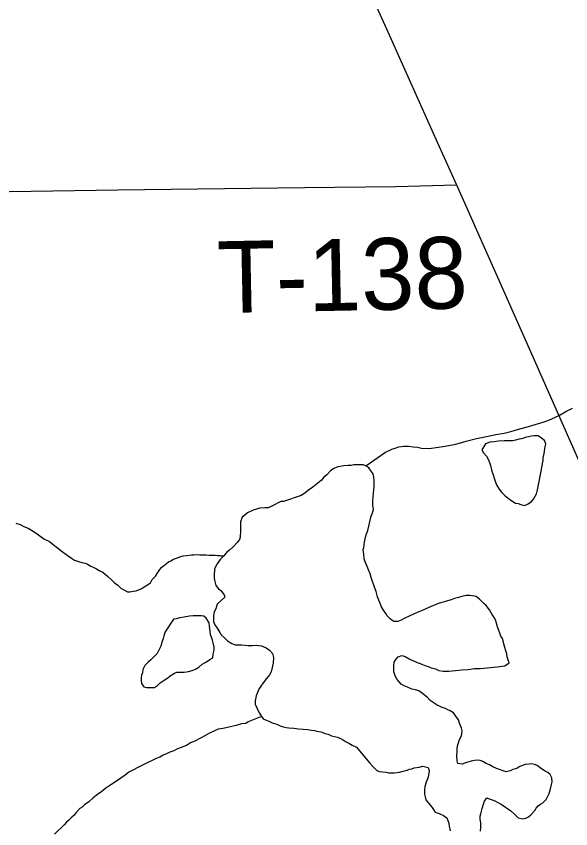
# Model space of a CAD drawing. Extents: x 10.6 to 44.6, y -2.6 to 23.4.
# Drawn here: x 19.078 to 19.517, y 20.958 to 21.601 of the extents above; entities that cross this region are included whole.
import ezdxf

# ---------------------------------------------------------------- set-up
doc = ezdxf.new("R2010")
doc.units = 0
for name, color, linetype in [('GM_X_Minor_Lake', 7, 'Continuous'), ('GM_X_Minor_River', 7, 'Continuous'), ('GM_X_State_Route', 7, 'Continuous'), ('GM_X_Township_Road', 7, 'Continuous'), ('GM_X_Township_Road_Text', 7, 'Continuous')]:
    doc.layers.add(name, color=color, linetype=linetype)

msp = doc.modelspace()

# ---------------------------------------------------------------- linework, layer by layer
at = {"layer": 'GM_X_Minor_Lake'}
for points in [[(19.49489, 21.24647), (19.49496, 21.24686), (19.49532, 21.24914), (19.49531, 21.25142), (19.49604, 21.25484), (19.4964, 21.25675), (19.49677, 21.25865), (19.4975, 21.26245), (19.49634, 21.2651), (19.49405, 21.26699), (19.49138, 21.26887), (19.48834, 21.26884), (19.48606, 21.26845), (19.48379, 21.26805), (19.4819, 21.26766), (19.48001, 21.26688), (19.47811, 21.26649), (19.47622, 21.26609), (19.47357, 21.26532), (19.47129, 21.26492), (19.46826, 21.2649), (19.46446, 21.26487), (19.45991, 21.26446), (19.4565, 21.26405), (19.45309, 21.26365), (19.44968, 21.26248), (19.44672, 21.25759)], [(19.44672, 21.25759), (19.44821, 21.25525), (19.45051, 21.25261), (19.45167, 21.25034), (19.45283, 21.24769), (19.4536, 21.24541), (19.45478, 21.24086), (19.45556, 21.23859), (19.45673, 21.23442), (19.4575, 21.23215), (19.45866, 21.22949), (19.46097, 21.22571), (19.4625, 21.22383), (19.46518, 21.22119), (19.46861, 21.21855), (19.47128, 21.21667), (19.47357, 21.21555), (19.47547, 21.21518), (19.47775, 21.21444), (19.4808, 21.2137), (19.48344, 21.21486), (19.48608, 21.21678), (19.48759, 21.21869), (19.48909, 21.22098), (19.49021, 21.22289), (19.49095, 21.22593), (19.49131, 21.22859), (19.49204, 21.23126), (19.49489, 21.24647)], [(19.45914, 21.11743), (19.45836, 21.12046), (19.45758, 21.12311), (19.45643, 21.125), (19.45489, 21.12727), (19.45297, 21.13106), (19.45028, 21.13446), (19.44838, 21.13596), (19.44493, 21.13936), (19.44226, 21.14162), (19.43922, 21.14198), (19.43732, 21.14234), (19.43428, 21.14232), (19.43087, 21.14153), (19.42822, 21.14075), (19.42519, 21.13997), (19.42255, 21.13881), (19.41952, 21.13803), (19.41724, 21.13725), (19.41497, 21.13686), (19.41232, 21.13608), (19.40967, 21.13492), (19.40665, 21.13376), (19.40249, 21.13183), (19.39908, 21.13028), (19.39605, 21.12912), (19.38584, 21.12449), (19.38282, 21.12295), (19.38017, 21.12179), (19.37713, 21.12176), (19.37446, 21.12364), (19.37179, 21.12628), (19.37063, 21.12817), (19.36871, 21.13082), (19.36718, 21.13347), (19.36563, 21.13726), (19.36408, 21.14142), (19.36291, 21.14559), (19.36174, 21.14901), (19.36097, 21.15128), (19.36019, 21.15355), (19.35903, 21.15658), (19.35824, 21.15962), (19.35708, 21.16265), (19.35592, 21.1653), (19.35515, 21.16719), (19.35438, 21.16909), (19.3536, 21.17136), (19.35319, 21.17516), (19.35279, 21.17857), (19.35315, 21.18048), (19.35352, 21.18238), (19.35388, 21.18466), (19.35461, 21.18846), (19.35535, 21.19113), (19.35646, 21.1938), (19.35757, 21.19836), (19.35867, 21.20331), (19.35903, 21.20521), (19.35978, 21.20712), (19.36089, 21.21054), (19.36049, 21.21396), (19.36046, 21.217), (19.36079, 21.22346), (19.36151, 21.22841), (19.36147, 21.23334), (19.36107, 21.236), (19.36067, 21.23866), (19.35914, 21.24092), (19.35722, 21.24357), (19.35493, 21.24507), (19.35265, 21.24582), (19.34999, 21.2458), (19.34771, 21.24578), (19.34544, 21.24576), (19.34316, 21.24537), (19.34089, 21.24535), (19.33747, 21.24494), (19.33444, 21.24454), (19.33255, 21.24415), (19.32952, 21.24299), (19.32688, 21.24107), (19.32386, 21.23801), (19.3216, 21.23609), (19.31934, 21.23341), (19.31557, 21.23035), (19.31293, 21.22805), (19.30954, 21.22574), (19.30652, 21.22344), (19.30366, 21.22163)], [(19.30366, 21.22163), (19.28949, 21.21686), (19.28949, 21.21686), (19.28759, 21.21684), (19.28041, 21.21299), (19.27738, 21.21183), (19.27473, 21.21181), (19.27094, 21.21141), (19.26563, 21.20985), (19.26109, 21.20791), (19.25883, 21.206), (19.25695, 21.20446), (19.25546, 21.20066), (19.25549, 21.19724), (19.25551, 21.19382), (19.25517, 21.1885), (19.25481, 21.18659), (19.25293, 21.1843), (19.24991, 21.18124), (19.2469, 21.17818), (19.24464, 21.17664), (19.242, 21.17358), (19.23937, 21.1709), (19.23712, 21.16747), (19.23562, 21.16518), (19.23487, 21.16327), (19.23453, 21.15833), (19.23455, 21.15643), (19.23494, 21.15453), (19.23611, 21.15036), (19.23803, 21.14772), (19.23994, 21.14621), (19.24262, 21.14281), (19.24302, 21.14092), (19.23698, 21.13555), (19.23587, 21.13175), (19.23475, 21.12946), (19.23402, 21.12641), (19.23405, 21.12186), (19.23521, 21.1192), (19.23713, 21.11656), (19.23905, 21.11315), (19.24021, 21.11126), (19.2425, 21.109), (19.24518, 21.10636), (19.24861, 21.10449), (19.25127, 21.10337), (19.25393, 21.10339), (19.25621, 21.1034), (19.25887, 21.10304), (19.26152, 21.10268), (19.26494, 21.10271), (19.26797, 21.10311), (19.26988, 21.10274), (19.27216, 21.10238), (19.27406, 21.10163), (19.27596, 21.10089), (19.27863, 21.09901), (19.28093, 21.09636), (19.28171, 21.09333), (19.28137, 21.08877), (19.28063, 21.08534), (19.2799, 21.08192), (19.2784, 21.07963), (19.27615, 21.07657), (19.27352, 21.07313), (19.27164, 21.07046), (19.27014, 21.06817), (19.26902, 21.0655), (19.26791, 21.06284), (19.26717, 21.05903), (19.2672, 21.05637), (19.26836, 21.05334), (19.26913, 21.05145), (19.27067, 21.04918), (19.2722, 21.04653), (19.27336, 21.04464), (19.27526, 21.04389), (19.27793, 21.04277), (19.28059, 21.04165), (19.28439, 21.04054), (19.28706, 21.03904), (19.28934, 21.0383), (19.29163, 21.03793), (19.29391, 21.03757), (19.2977, 21.03722), (19.3015, 21.03687), (19.3053, 21.03652)], [(19.20254, 21.12352), (19.19578, 21.1136), (19.19467, 21.11055), (19.19431, 21.10827), (19.19319, 21.10522), (19.19246, 21.10217), (19.19096, 21.09951), (19.18946, 21.09645), (19.18683, 21.09377), (19.18457, 21.09148), (19.18231, 21.08956), (19.17967, 21.08688), (19.17817, 21.08383), (19.17782, 21.08117), (19.17707, 21.07927), (19.17671, 21.07737), (19.17673, 21.07509), (19.17712, 21.07281), (19.17904, 21.07016), (19.18094, 21.06942), (19.1836, 21.06944), (19.1855, 21.06945), (19.1874, 21.06947), (19.18966, 21.071), (19.19192, 21.0733), (19.19494, 21.07522), (19.19796, 21.07714), (19.19985, 21.07867), (19.20325, 21.08098), (19.20514, 21.08175), (19.20741, 21.08177), (19.21083, 21.08179), (19.21424, 21.0822), (19.21727, 21.08298), (19.21992, 21.08414), (19.22257, 21.08568), (19.2252, 21.08798), (19.22861, 21.0899), (19.23125, 21.09182), (19.23352, 21.09298), (19.23387, 21.09602), (19.23461, 21.09906), (19.23459, 21.10134), (19.23381, 21.10476), (19.23341, 21.10703), (19.23263, 21.10931), (19.23186, 21.1112), (19.23145, 21.11424), (19.23105, 21.11803), (19.23065, 21.12069), (19.22834, 21.12447), (19.22643, 21.12598), (19.22453, 21.12634), (19.21808, 21.1263), (19.21505, 21.12589), (19.21088, 21.1251), (19.20746, 21.1247), (19.20443, 21.12392), (19.20254, 21.12352)], [(19.20514, 21.08175), (19.20741, 21.08177), (19.21083, 21.08179), (19.21424, 21.0822), (19.21727, 21.08298), (19.21992, 21.08414), (19.22257, 21.08568), (19.2252, 21.08798), (19.22861, 21.0899), (19.23125, 21.09182), (19.23352, 21.09298), (19.23387, 21.09602), (19.23461, 21.09906), (19.23459, 21.10134), (19.23381, 21.10476), (19.23341, 21.10703), (19.23263, 21.10931), (19.23186, 21.1112), (19.23145, 21.11424), (19.23105, 21.11803), (19.23065, 21.12069), (19.22834, 21.12447), (19.22643, 21.12598), (19.22453, 21.12634), (19.21808, 21.1263), (19.21505, 21.12589), (19.21088, 21.1251), (19.20746, 21.1247), (19.20443, 21.12392), (19.20254, 21.12352)], [(19.20254, 21.12352), (19.19578, 21.1136), (19.19467, 21.11055), (19.19431, 21.10827), (19.19319, 21.10522), (19.19246, 21.10217), (19.19096, 21.09951), (19.18946, 21.09645), (19.18683, 21.09377), (19.18457, 21.09148), (19.18231, 21.08956), (19.17967, 21.08688), (19.17817, 21.08383), (19.17782, 21.08117), (19.17707, 21.07927), (19.17671, 21.07737), (19.17673, 21.07509), (19.17712, 21.07281), (19.17904, 21.07016), (19.18094, 21.06942), (19.1836, 21.06944), (19.1855, 21.06945), (19.1874, 21.06947), (19.18966, 21.071), (19.19192, 21.0733), (19.19494, 21.07522), (19.19796, 21.07714), (19.19985, 21.07867), (19.20325, 21.08098), (19.20514, 21.08175)], [(19.49912, 21.00222), (19.49683, 21.00334), (19.49416, 21.00522), (19.49073, 21.00786), (19.48845, 21.0086), (19.48616, 21.00897), (19.48389, 21.00895), (19.48123, 21.00855), (19.47821, 21.00739), (19.47631, 21.00661), (19.47443, 21.00546), (19.4714, 21.00468), (19.46913, 21.00352), (19.4661, 21.00274), (19.45849, 21.00534), (19.45544, 21.00684), (19.45277, 21.00834), (19.45011, 21.00946), (19.44744, 21.01096), (19.44553, 21.01171), (19.44363, 21.01207), (19.44098, 21.01167), (19.43833, 21.01127), (19.43454, 21.01011), (19.43113, 21.00894), (19.42772, 21.0093), (19.42732, 21.01157), (19.42691, 21.01537), (19.42726, 21.01917), (19.42725, 21.02107), (19.42761, 21.02335), (19.42835, 21.02564), (19.42909, 21.02831), (19.43058, 21.03135), (19.43131, 21.03516), (19.43054, 21.03743), (19.42899, 21.04122), (19.42821, 21.04387), (19.42629, 21.0469), (19.42437, 21.04955), (19.4217, 21.05104), (19.4198, 21.05179), (19.41789, 21.05292), (19.41523, 21.05366), (19.41332, 21.05478), (19.41142, 21.05553), (19.4057, 21.05929), (19.40378, 21.06155), (19.40111, 21.06381), (19.39882, 21.06569), (19.39691, 21.06682), (19.39425, 21.06756), (19.39121, 21.0683), (19.38778, 21.06979), (19.38512, 21.07091), (19.38283, 21.07204), (19.3813, 21.07392), (19.37976, 21.07581), (19.37861, 21.0777), (19.37784, 21.0796), (19.37706, 21.08187), (19.37704, 21.08453), (19.37702, 21.08681), (19.37738, 21.08947), (19.3785, 21.09176), (19.38039, 21.09367), (19.38341, 21.09484), (19.38608, 21.09409), (19.38913, 21.09222), (19.39141, 21.09109), (19.39332, 21.09035), (19.3956, 21.08923), (19.39788, 21.08848), (19.39979, 21.08774), (19.40245, 21.08662), (19.40435, 21.08625), (19.40664, 21.08513), (19.41006, 21.08439), (19.41273, 21.08289), (19.41615, 21.08254), (19.4207, 21.08257), (19.42601, 21.08299), (19.43094, 21.08341), (19.43587, 21.08382), (19.4408, 21.08462), (19.44573, 21.08465), (19.45901, 21.08589), (19.46507, 21.0867), (19.46847, 21.089), (19.4677, 21.09127), (19.46691, 21.09393), (19.46652, 21.0962), (19.46574, 21.09848), (19.46496, 21.10113), (19.46418, 21.10416), (19.46378, 21.10644), (19.46301, 21.10834), (19.46186, 21.11023), (19.46108, 21.1125), (19.4603, 21.11477), (19.45914, 21.11743)], [(19.3053, 21.03652), (19.30872, 21.03616), (19.31176, 21.0358), (19.31404, 21.03544), (19.31594, 21.03507), (19.31936, 21.03434), (19.32241, 21.03322), (19.32507, 21.03248), (19.32773, 21.03136), (19.33001, 21.03062), (19.33229, 21.03026), (19.3342, 21.02951), (19.33648, 21.02839), (19.33877, 21.02688), (19.34144, 21.02538), (19.34411, 21.02388), (19.34754, 21.02239), (19.34984, 21.01936), (19.35788, 21.00955), (19.36018, 21.00728), (19.36362, 21.00389), (19.36552, 21.00314), (19.36818, 21.00278), (19.37084, 21.00242), (19.37274, 21.00206), (19.37578, 21.00208), (19.37767, 21.00209), (19.37957, 21.00211), (19.38147, 21.0025), (19.3845, 21.00328), (19.38753, 21.00406), (19.38942, 21.00484), (19.39131, 21.00523), (19.3932, 21.006), (19.397, 21.00641), (19.40003, 21.0072), (19.40421, 21.00609), (19.40499, 21.00343), (19.40427, 20.99849), (19.40278, 20.99468), (19.40167, 20.99125), (19.40131, 20.98859), (19.40133, 20.98517), (19.40173, 20.98289), (19.40251, 20.98062), (19.40443, 20.97797), (19.40749, 20.97458), (19.4098, 20.97079), (19.41284, 20.96968), (19.41627, 20.96818), (19.41894, 20.9663), (19.42049, 20.96213), (19.42088, 20.95986), (19.42167, 20.95606)], [(19.44558, 20.95586), (19.44594, 20.9589), (19.44591, 20.96232), (19.44551, 20.96536), (19.44549, 20.96763), (19.44586, 20.96954), (19.44696, 20.97373), (19.44808, 20.97715), (19.44882, 20.97944), (19.4507, 20.98211), (19.4526, 20.98136), (19.45564, 20.98025), (19.45755, 20.9795), (19.45945, 20.97838), (19.46212, 20.97726), (19.46975, 20.97199), (19.47281, 20.96897), (19.47549, 20.96634), (19.47891, 20.9656), (19.48156, 20.966), (19.48383, 20.96716), (19.48571, 20.96869), (19.48873, 20.97213), (19.48985, 20.97404), (19.49135, 20.97595), (19.49324, 20.9771), (19.49513, 20.97826), (19.49777, 20.98094), (19.49889, 20.98284), (19.50001, 20.98551), (19.50075, 20.98742), (19.50112, 20.98932), (19.50185, 20.99274), (19.50259, 20.99503), (19.50219, 20.99806), (19.50103, 21.00072), (19.49912, 21.00222)]]:
    msp.add_lwpolyline(points, dxfattribs=at)
at = {"layer": 'GM_X_Minor_River'}
for points in [[(19.35493, 21.24507), (19.37041, 21.25582), (19.37268, 21.25698), (19.37532, 21.25814), (19.37798, 21.25892), (19.381, 21.26008), (19.38479, 21.26049), (19.38897, 21.26052), (19.39239, 21.26016), (19.39581, 21.25981), (19.39885, 21.25907), (19.40492, 21.25874), (19.41061, 21.25954), (19.41781, 21.26073), (19.42615, 21.26231), (19.43448, 21.26465), (19.44243, 21.26661), (19.45039, 21.26819), (19.45797, 21.26976), (19.46441, 21.27095), (19.46972, 21.27213), (19.47502, 21.27369), (19.48184, 21.27563), (19.49622, 21.27992), (19.50039, 21.28147), (19.50455, 21.2834), (19.50871, 21.28533), (19.51324, 21.28802), (19.51853, 21.29072)], [(19.07747, 21.19973), (19.08089, 21.19862), (19.08394, 21.19712), (19.08737, 21.19562), (19.09118, 21.19337), (19.09538, 21.19036), (19.09958, 21.18735), (19.10415, 21.18511), (19.1072, 21.18285), (19.11064, 21.18022), (19.11408, 21.1772), (19.11827, 21.17419), (19.12171, 21.17194), (19.124, 21.17044), (19.12704, 21.16932), (19.1297, 21.16858), (19.13237, 21.16784), (19.13427, 21.16709), (19.13694, 21.16559), (19.13922, 21.16447), (19.14151, 21.16335), (19.14341, 21.16222), (19.14646, 21.16072), (19.15028, 21.15733)], [(19.15028, 21.15733), (19.15296, 21.15507), (19.15564, 21.15243), (19.15831, 21.15055), (19.1606, 21.14829), (19.16594, 21.14529), (19.16784, 21.14531), (19.17049, 21.1457), (19.17276, 21.1461), (19.17465, 21.14687), (19.17692, 21.14765), (19.17919, 21.14919), (19.18184, 21.15073), (19.1841, 21.15226), (19.1856, 21.15493), (19.18824, 21.15761), (19.19011, 21.16066), (19.19161, 21.16295), (19.19311, 21.16487), (19.19576, 21.16678), (19.19839, 21.16908), (19.20029, 21.16986), (19.20255, 21.17101), (19.20558, 21.17217), (19.20747, 21.17295), (19.21012, 21.17373), (19.21278, 21.17413), (19.21657, 21.17454), (19.21847, 21.17455), (19.22074, 21.17495), (19.2234, 21.17459), (19.2253, 21.1746), (19.22833, 21.17462), (19.23061, 21.17426), (19.23251, 21.17427), (19.23555, 21.17429), (19.242, 21.17358), (19.23707, 21.17392)], [(19.2722, 21.04653), (19.26161, 21.04227), (19.25972, 21.04112), (19.25631, 21.04072), (19.25214, 21.03955), (19.24874, 21.03876), (19.24532, 21.03798), (19.24153, 21.03719), (19.23775, 21.0364), (19.23434, 21.03486), (19.23094, 21.03331), (19.22716, 21.03138), (19.22338, 21.02908), (19.21922, 21.02715), (19.21582, 21.0256), (19.2128, 21.02368), (19.20863, 21.02213), (19.20561, 21.02097), (19.20258, 21.01943), (19.19955, 21.01827), (19.19691, 21.0171), (19.19426, 21.01595), (19.19161, 21.01441), (19.18859, 21.01325), (19.18556, 21.0117), (19.18216, 21.01016), (19.17838, 21.00823), (19.17422, 21.0063), (19.17081, 21.00438), (19.16704, 21.00245), (19.16402, 21.00015), (19.16062, 20.99784), (19.15647, 20.99477), (19.15269, 20.99247), (19.14891, 20.98978), (19.14552, 20.98709), (19.14212, 20.98479), (19.13873, 20.98211), (19.13534, 20.97904), (19.13194, 20.97674), (19.13005, 20.97482), (19.12816, 20.97367), (19.12516, 20.97023), (19.12365, 20.96832), (19.12177, 20.96678), (19.11988, 20.96487), (19.11762, 20.96295), (19.11574, 20.96066), (19.10821, 20.95339)]]:
    msp.add_lwpolyline(points, dxfattribs=at)
at = {"layer": 'GM_X_State_Route'}
msp.add_lwpolyline([(19.65791, 20.95269), (19.62559, 21.02251), (19.55122, 21.18714), (19.48342, 21.34011), (19.42685, 21.46724), (19.41202, 21.5005), (19.37155, 21.59076), (19.33935, 21.66174)], dxfattribs=at)
at = {"layer": 'GM_X_Township_Road'}
msp.add_lwpolyline([(19.42685, 21.46724), (19.37854, 21.46597), (19.30629, 21.46512), (19.1584, 21.46321), (19.02068, 21.46109), (19.00322, 21.46045), (18.92381, 21.45913), (18.87005, 21.45866), (18.81063, 21.45748), (18.7716, 21.45705), (18.74201, 21.45677), (18.70786, 21.45603), (18.67646, 21.45606), (18.64227, 21.45441), (18.5206, 21.45253), (18.38478, 21.45041), (18.35035, 21.4497), (18.26877, 21.44805), (18.23151, 21.44758), (18.20817, 21.44734), (18.19923, 21.44718)], dxfattribs=at)

# ---------------------------------------------------------------- texts
at = {"layer": 'GM_X_Township_Road_Text'}
msp.add_text('T-138', height=0.056818, rotation=1.12293, dxfattribs=at).set_placement((19.23762, 21.36594))

doc.saveas('drawing.dxf')
